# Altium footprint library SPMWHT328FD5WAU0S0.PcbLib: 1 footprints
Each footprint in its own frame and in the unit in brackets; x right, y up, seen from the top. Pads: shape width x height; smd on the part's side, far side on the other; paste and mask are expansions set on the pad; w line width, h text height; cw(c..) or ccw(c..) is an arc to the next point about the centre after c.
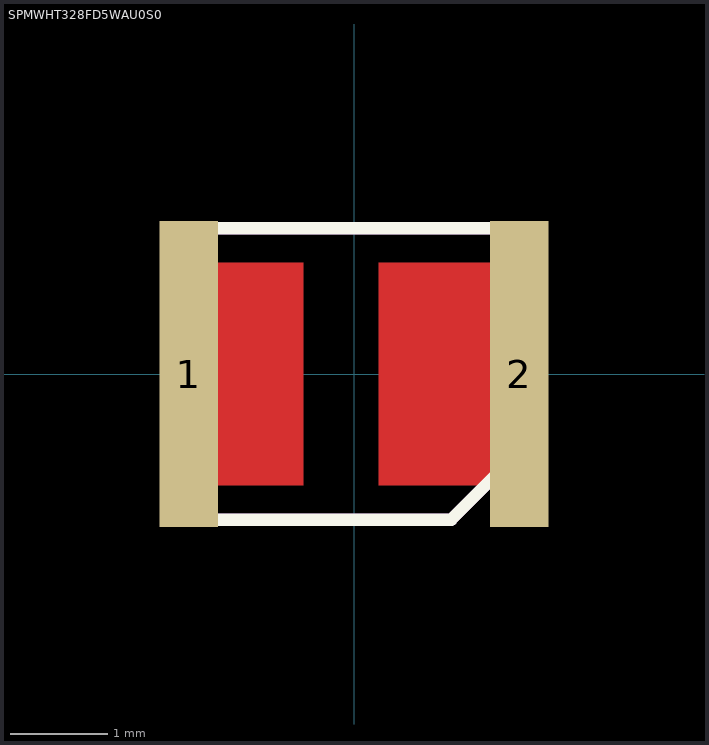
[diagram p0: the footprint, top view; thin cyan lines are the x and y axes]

## SPMWHT328FD5WAU0S0 [mm] "Samsung LED P/N SPMWHT328FD5WAU0S0"
height 0.65
pads (2):
  rect 0.6x3.15 smd: 1(-1.7,0) 2(1.7,0)
Top Layer:
  region: 1.8,1.15 0.25,1.15 0.25,-1.15 1.8,-1.15
  rectangle: -1.8,-1.15 -0.52,1.15
Top Overlay:
  lines w0.127: -1.5,-1.5 -1.5,1.5 1.5,1.5 1.5,-1 1,-1.5 -1.5,-1.5
Top Solder:
  region: 1.8,1.2 0.2,1.2 0.2,-1.2 1.8,-1.2
  rectangle: -1.8,-1.2 -0.45,1.2
M5 Assembly Top:
  lines w0.127: -1.5,-1.5 1,-1.5 1.5,-1 1.5,1.5 -1.5,1.5 -1.5,-1.5
  text ".Designator" at -0.1,-0.1 h1.52
3D body: height 0.5, standoff 0, extent -1.5,-1.5 1.5,1.5
3D body: height 0.65, standoff 0.5, extent -1.3,-1.3 1.3,1.3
